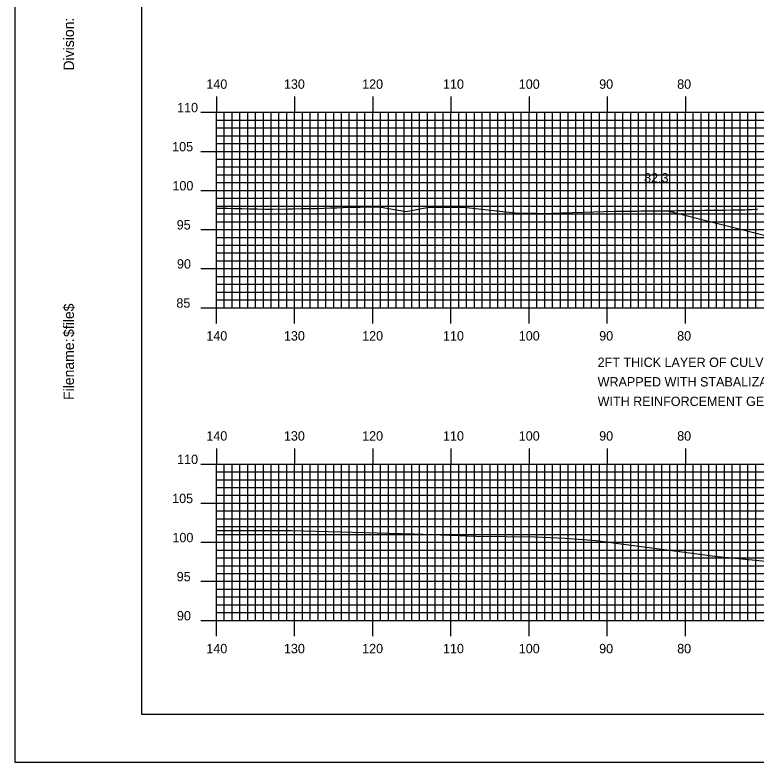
# Model space of a CAD drawing. Extents: x 1774777 to 1775120, y 442591 to 442811.
# Drawn here: x 1774776.9 to 1774871.7, y 442590.5 to 442686.1 of the extents above; entities that cross this region are included whole.
import ezdxf

# ---------------------------------------------------------------- set-up
doc = ezdxf.new("R2010")
doc.units = 0
for name, color, linetype in [('BORDER', 7, 'Continuous'), ('D_Roadway_FinishedGrade', 7, 'Continuous'), ('D_Text_Standard', 7, 'Continuous'), ('H_V ANNOTATION', 7, 'Continuous'), ('MAJOR', 7, 'Continuous'), ('MINOR', 7, 'Continuous'), ('PLOT BOUNDARY', 7, 'Continuous'), ('S_Roadway_Centerline', 7, 'Continuous')]:
    doc.layers.add(name, color=color, linetype=linetype)

msp = doc.modelspace()

# ---------------------------------------------------------------- linework, layer by layer
at = {"layer": 'BORDER'}
msp.add_lwpolyline([(1774793.085, 442596.665), (1775113.085, 442596.665), (1775113.085, 442806.665), (1774793.085, 442806.665)], close=True, dxfattribs=at)
at = {"layer": 'D_Roadway_FinishedGrade'}
for p, q in [((1774871.566, 442661.25), (1774871.566, 442661.25)), ((1774873.784, 442657.665), (1774860.231, 442661.061))]:
    msp.add_line(p, q, dxfattribs=at)
at = {"layer": 'MAJOR'}
for p, q in [((1774802.685, 442675.669), (1774802.685, 442673.665)), ((1774812.685, 442675.669), (1774812.685, 442673.665)), ((1774822.685, 442675.669), (1774822.685, 442673.665)), ((1774832.685, 442675.669), (1774832.685, 442673.665)), ((1774842.685, 442675.669), (1774842.685, 442673.665)), ((1774852.685, 442675.669), (1774852.685, 442673.665)), ((1774862.685, 442675.669), (1774862.685, 442673.665)), ((1774800.681, 442673.665), (1774802.685, 442673.665)), ((1774802.685, 442673.665), (1775082.685, 442673.665)), ((1774802.685, 442648.665), (1774802.685, 442673.665)), ((1774802.685, 442648.665), (1774802.685, 442673.665)), ((1774802.685, 442673.665), (1775082.685, 442673.665)), ((1774812.685, 442648.665), (1774812.685, 442673.665)), ((1774822.685, 442648.665), (1774822.685, 442673.665)), ((1774832.685, 442648.665), (1774832.685, 442673.665)), ((1774842.685, 442648.665), (1774842.685, 442673.665)), ((1774852.685, 442648.665), (1774852.685, 442673.665)), ((1774862.685, 442648.665), (1774862.685, 442673.665)), ((1774800.681, 442668.665), (1774802.685, 442668.665)), ((1774802.685, 442668.665), (1775082.685, 442668.665)), ((1774800.681, 442663.665), (1774802.685, 442663.665)), ((1774802.685, 442663.665), (1775082.685, 442663.665)), ((1774800.681, 442658.665), (1774802.685, 442658.665)), ((1774802.685, 442658.665), (1775082.685, 442658.665)), ((1774800.681, 442653.665), (1774802.685, 442653.665)), ((1774802.685, 442653.665), (1775082.685, 442653.665)), ((1774800.681, 442648.665), (1774802.685, 442648.665)), ((1774802.685, 442648.665), (1775082.685, 442648.665)), ((1774802.685, 442648.665), (1775082.685, 442648.665)), ((1774802.685, 442646.661), (1774802.685, 442648.665)), ((1774812.685, 442646.661), (1774812.685, 442648.665)), ((1774822.685, 442646.661), (1774822.685, 442648.665)), ((1774832.685, 442646.661), (1774832.685, 442648.665)), ((1774842.685, 442646.661), (1774842.685, 442648.665)), ((1774852.685, 442646.661), (1774852.685, 442648.665)), ((1774862.685, 442646.661), (1774862.685, 442648.665)), ((1774802.685, 442630.669), (1774802.685, 442628.665)), ((1774812.685, 442630.669), (1774812.685, 442628.665)), ((1774822.685, 442630.669), (1774822.685, 442628.665)), ((1774832.685, 442630.669), (1774832.685, 442628.665)), ((1774842.685, 442630.669), (1774842.685, 442628.665)), ((1774852.685, 442630.669), (1774852.685, 442628.665)), ((1774862.685, 442630.669), (1774862.685, 442628.665)), ((1774800.681, 442628.665), (1774802.685, 442628.665)), ((1774802.685, 442628.665), (1775082.685, 442628.665)), ((1774802.685, 442608.665), (1774802.685, 442628.665)), ((1774802.685, 442608.665), (1774802.685, 442628.665)), ((1774802.685, 442628.665), (1775082.685, 442628.665)), ((1774812.685, 442608.665), (1774812.685, 442628.665)), ((1774822.685, 442608.665), (1774822.685, 442628.665)), ((1774832.685, 442608.665), (1774832.685, 442628.665)), ((1774842.685, 442608.665), (1774842.685, 442628.665)), ((1774852.685, 442608.665), (1774852.685, 442628.665)), ((1774862.685, 442608.665), (1774862.685, 442628.665)), ((1774800.681, 442623.665), (1774802.685, 442623.665)), ((1774802.685, 442623.665), (1775082.685, 442623.665)), ((1774800.681, 442618.665), (1774802.685, 442618.665)), ((1774802.685, 442618.665), (1775082.685, 442618.665)), ((1774800.681, 442613.665), (1774802.685, 442613.665)), ((1774802.685, 442613.665), (1775082.685, 442613.665)), ((1774800.681, 442608.665), (1774802.685, 442608.665)), ((1774802.685, 442608.665), (1775082.685, 442608.665)), ((1774802.685, 442608.665), (1775082.685, 442608.665)), ((1774802.685, 442606.661), (1774802.685, 442608.665)), ((1774812.685, 442606.661), (1774812.685, 442608.665)), ((1774822.685, 442606.661), (1774822.685, 442608.665)), ((1774832.685, 442606.661), (1774832.685, 442608.665)), ((1774842.685, 442606.661), (1774842.685, 442608.665)), ((1774852.685, 442606.661), (1774852.685, 442608.665)), ((1774862.685, 442606.661), (1774862.685, 442608.665))]:
    msp.add_line(p, q, dxfattribs=at)
at = {"layer": 'MINOR'}
for p, q in [((1774803.685, 442648.665), (1774803.685, 442673.665)), ((1774804.685, 442648.665), (1774804.685, 442673.665)), ((1774805.685, 442648.665), (1774805.685, 442673.665)), ((1774806.685, 442648.665), (1774806.685, 442673.665)), ((1774807.685, 442648.665), (1774807.685, 442673.665)), ((1774808.685, 442648.665), (1774808.685, 442673.665)), ((1774809.685, 442648.665), (1774809.685, 442673.665)), ((1774810.685, 442648.665), (1774810.685, 442673.665)), ((1774811.685, 442648.665), (1774811.685, 442673.665)), ((1774813.685, 442648.665), (1774813.685, 442673.665)), ((1774814.685, 442648.665), (1774814.685, 442673.665)), ((1774815.685, 442648.665), (1774815.685, 442673.665)), ((1774816.685, 442648.665), (1774816.685, 442673.665)), ((1774817.685, 442648.665), (1774817.685, 442673.665)), ((1774818.685, 442648.665), (1774818.685, 442673.665)), ((1774819.685, 442648.665), (1774819.685, 442673.665)), ((1774820.685, 442648.665), (1774820.685, 442673.665)), ((1774821.685, 442648.665), (1774821.685, 442673.665)), ((1774823.685, 442648.665), (1774823.685, 442673.665)), ((1774824.685, 442648.665), (1774824.685, 442673.665)), ((1774825.685, 442648.665), (1774825.685, 442673.665)), ((1774826.685, 442648.665), (1774826.685, 442673.665)), ((1774827.685, 442648.665), (1774827.685, 442673.665)), ((1774828.685, 442648.665), (1774828.685, 442673.665)), ((1774829.685, 442648.665), (1774829.685, 442673.665)), ((1774830.685, 442648.665), (1774830.685, 442673.665)), ((1774831.685, 442648.665), (1774831.685, 442673.665)), ((1774833.685, 442648.665), (1774833.685, 442673.665)), ((1774834.685, 442648.665), (1774834.685, 442673.665)), ((1774835.685, 442648.665), (1774835.685, 442673.665)), ((1774836.685, 442648.665), (1774836.685, 442673.665)), ((1774837.685, 442648.665), (1774837.685, 442673.665)), ((1774838.685, 442648.665), (1774838.685, 442673.665)), ((1774839.685, 442648.665), (1774839.685, 442673.665)), ((1774840.685, 442648.665), (1774840.685, 442673.665)), ((1774841.685, 442648.665), (1774841.685, 442673.665)), ((1774843.685, 442648.665), (1774843.685, 442673.665)), ((1774844.685, 442648.665), (1774844.685, 442673.665)), ((1774845.685, 442648.665), (1774845.685, 442673.665)), ((1774846.685, 442648.665), (1774846.685, 442673.665)), ((1774847.685, 442648.665), (1774847.685, 442673.665)), ((1774848.685, 442648.665), (1774848.685, 442673.665)), ((1774849.685, 442648.665), (1774849.685, 442673.665)), ((1774850.685, 442648.665), (1774850.685, 442673.665)), ((1774851.685, 442648.665), (1774851.685, 442673.665)), ((1774853.685, 442648.665), (1774853.685, 442673.665)), ((1774854.685, 442648.665), (1774854.685, 442673.665)), ((1774855.685, 442648.665), (1774855.685, 442673.665)), ((1774856.685, 442648.665), (1774856.685, 442673.665)), ((1774857.685, 442648.665), (1774857.685, 442673.665)), ((1774858.685, 442648.665), (1774858.685, 442673.665)), ((1774859.685, 442648.665), (1774859.685, 442673.665)), ((1774860.685, 442648.665), (1774860.685, 442673.665)), ((1774861.685, 442648.665), (1774861.685, 442673.665)), ((1774863.685, 442648.665), (1774863.685, 442673.665)), ((1774864.685, 442648.665), (1774864.685, 442673.665)), ((1774865.685, 442648.665), (1774865.685, 442673.665)), ((1774866.685, 442648.665), (1774866.685, 442673.665)), ((1774867.685, 442648.665), (1774867.685, 442673.665)), ((1774868.685, 442648.665), (1774868.685, 442673.665)), ((1774869.685, 442648.665), (1774869.685, 442673.665)), ((1774870.685, 442648.665), (1774870.685, 442673.665)), ((1774871.685, 442648.665), (1774871.685, 442673.665)), ((1774802.685, 442672.665), (1775082.685, 442672.665)), ((1774802.685, 442672.665), (1774804.689, 442672.665)), ((1774802.685, 442671.665), (1775082.685, 442671.665)), ((1774802.685, 442671.665), (1774804.689, 442671.665)), ((1774802.685, 442670.665), (1775082.685, 442670.665)), ((1774802.685, 442670.665), (1774804.689, 442670.665)), ((1774802.685, 442669.665), (1775082.685, 442669.665)), ((1774802.685, 442669.665), (1774804.689, 442669.665)), ((1774802.685, 442667.665), (1775082.685, 442667.665)), ((1774802.685, 442667.665), (1774804.689, 442667.665)), ((1774802.685, 442666.665), (1775082.685, 442666.665)), ((1774802.685, 442666.665), (1774804.689, 442666.665)), ((1774802.685, 442665.665), (1775082.685, 442665.665)), ((1774802.685, 442665.665), (1774804.689, 442665.665)), ((1774802.685, 442664.665), (1775082.685, 442664.665)), ((1774802.685, 442664.665), (1774804.689, 442664.665)), ((1774802.685, 442662.665), (1775082.685, 442662.665)), ((1774802.685, 442662.665), (1774804.689, 442662.665)), ((1774802.685, 442661.665), (1775082.685, 442661.665)), ((1774802.685, 442661.665), (1774804.689, 442661.665)), ((1774802.685, 442660.665), (1775082.685, 442660.665)), ((1774802.685, 442660.665), (1774804.689, 442660.665)), ((1774802.685, 442659.665), (1775082.685, 442659.665)), ((1774802.685, 442659.665), (1774804.689, 442659.665)), ((1774802.685, 442657.665), (1775082.685, 442657.665)), ((1774802.685, 442657.665), (1774804.689, 442657.665)), ((1774802.685, 442656.665), (1775082.685, 442656.665)), ((1774802.685, 442656.665), (1774804.689, 442656.665)), ((1774802.685, 442655.665), (1775082.685, 442655.665)), ((1774802.685, 442655.665), (1774804.689, 442655.665)), ((1774802.685, 442654.665), (1775082.685, 442654.665)), ((1774802.685, 442654.665), (1774804.689, 442654.665)), ((1774802.685, 442652.665), (1775082.685, 442652.665)), ((1774802.685, 442652.665), (1774804.689, 442652.665)), ((1774802.685, 442651.665), (1775082.685, 442651.665)), ((1774802.685, 442651.665), (1774804.689, 442651.665)), ((1774802.685, 442650.665), (1775082.685, 442650.665)), ((1774802.685, 442650.665), (1774804.689, 442650.665)), ((1774802.685, 442649.665), (1775082.685, 442649.665)), ((1774802.685, 442649.665), (1774804.689, 442649.665)), ((1774803.685, 442608.665), (1774803.685, 442628.665)), ((1774804.685, 442608.665), (1774804.685, 442628.665)), ((1774805.685, 442608.665), (1774805.685, 442628.665)), ((1774806.685, 442608.665), (1774806.685, 442628.665)), ((1774807.685, 442608.665), (1774807.685, 442628.665)), ((1774808.685, 442608.665), (1774808.685, 442628.665)), ((1774809.685, 442608.665), (1774809.685, 442628.665)), ((1774810.685, 442608.665), (1774810.685, 442628.665)), ((1774811.685, 442608.665), (1774811.685, 442628.665)), ((1774813.685, 442608.665), (1774813.685, 442628.665)), ((1774814.685, 442608.665), (1774814.685, 442628.665)), ((1774815.685, 442608.665), (1774815.685, 442628.665)), ((1774816.685, 442608.665), (1774816.685, 442628.665)), ((1774817.685, 442608.665), (1774817.685, 442628.665)), ((1774818.685, 442608.665), (1774818.685, 442628.665)), ((1774819.685, 442608.665), (1774819.685, 442628.665)), ((1774820.685, 442608.665), (1774820.685, 442628.665)), ((1774821.685, 442608.665), (1774821.685, 442628.665)), ((1774823.685, 442608.665), (1774823.685, 442628.665)), ((1774824.685, 442608.665), (1774824.685, 442628.665)), ((1774825.685, 442608.665), (1774825.685, 442628.665)), ((1774826.685, 442608.665), (1774826.685, 442628.665)), ((1774827.685, 442608.665), (1774827.685, 442628.665)), ((1774828.685, 442608.665), (1774828.685, 442628.665)), ((1774829.685, 442608.665), (1774829.685, 442628.665)), ((1774830.685, 442608.665), (1774830.685, 442628.665)), ((1774831.685, 442608.665), (1774831.685, 442628.665)), ((1774833.685, 442608.665), (1774833.685, 442628.665)), ((1774834.685, 442608.665), (1774834.685, 442628.665)), ((1774835.685, 442608.665), (1774835.685, 442628.665)), ((1774836.685, 442608.665), (1774836.685, 442628.665)), ((1774837.685, 442608.665), (1774837.685, 442628.665)), ((1774838.685, 442608.665), (1774838.685, 442628.665)), ((1774839.685, 442608.665), (1774839.685, 442628.665)), ((1774840.685, 442608.665), (1774840.685, 442628.665)), ((1774841.685, 442608.665), (1774841.685, 442628.665)), ((1774843.685, 442608.665), (1774843.685, 442628.665)), ((1774844.685, 442608.665), (1774844.685, 442628.665)), ((1774845.685, 442608.665), (1774845.685, 442628.665)), ((1774846.685, 442608.665), (1774846.685, 442628.665)), ((1774847.685, 442608.665), (1774847.685, 442628.665)), ((1774848.685, 442608.665), (1774848.685, 442628.665)), ((1774849.685, 442608.665), (1774849.685, 442628.665)), ((1774850.685, 442608.665), (1774850.685, 442628.665)), ((1774851.685, 442608.665), (1774851.685, 442628.665)), ((1774853.685, 442608.665), (1774853.685, 442628.665)), ((1774854.685, 442608.665), (1774854.685, 442628.665)), ((1774855.685, 442608.665), (1774855.685, 442628.665)), ((1774856.685, 442608.665), (1774856.685, 442628.665)), ((1774857.685, 442608.665), (1774857.685, 442628.665)), ((1774858.685, 442608.665), (1774858.685, 442628.665)), ((1774859.685, 442608.665), (1774859.685, 442628.665)), ((1774860.685, 442608.665), (1774860.685, 442628.665)), ((1774861.685, 442608.665), (1774861.685, 442628.665)), ((1774863.685, 442608.665), (1774863.685, 442628.665)), ((1774864.685, 442608.665), (1774864.685, 442628.665)), ((1774865.685, 442608.665), (1774865.685, 442628.665)), ((1774866.685, 442608.665), (1774866.685, 442628.665)), ((1774867.685, 442608.665), (1774867.685, 442628.665)), ((1774868.685, 442608.665), (1774868.685, 442628.665)), ((1774869.685, 442608.665), (1774869.685, 442628.665)), ((1774870.685, 442608.665), (1774870.685, 442628.665)), ((1774871.685, 442608.665), (1774871.685, 442628.665)), ((1774802.685, 442627.665), (1775082.685, 442627.665)), ((1774802.685, 442627.665), (1774804.689, 442627.665)), ((1774802.685, 442626.665), (1775082.685, 442626.665)), ((1774802.685, 442626.665), (1774804.689, 442626.665)), ((1774802.685, 442625.665), (1775082.685, 442625.665)), ((1774802.685, 442625.665), (1774804.689, 442625.665)), ((1774802.685, 442624.665), (1775082.685, 442624.665)), ((1774802.685, 442624.665), (1774804.689, 442624.665)), ((1774802.685, 442622.665), (1775082.685, 442622.665)), ((1774802.685, 442622.665), (1774804.689, 442622.665)), ((1774802.685, 442621.665), (1775082.685, 442621.665)), ((1774802.685, 442621.665), (1774804.689, 442621.665)), ((1774802.685, 442620.665), (1775082.685, 442620.665)), ((1774802.685, 442620.665), (1774804.689, 442620.665)), ((1774802.685, 442619.665), (1775082.685, 442619.665)), ((1774802.685, 442619.665), (1774804.689, 442619.665)), ((1774802.685, 442617.665), (1775082.685, 442617.665)), ((1774802.685, 442617.665), (1774804.689, 442617.665)), ((1774802.685, 442616.665), (1775082.685, 442616.665)), ((1774802.685, 442616.665), (1774804.689, 442616.665)), ((1774802.685, 442615.665), (1775082.685, 442615.665)), ((1774802.685, 442615.665), (1774804.689, 442615.665)), ((1774802.685, 442614.665), (1775082.685, 442614.665)), ((1774802.685, 442614.665), (1774804.689, 442614.665)), ((1774802.685, 442612.665), (1775082.685, 442612.665)), ((1774802.685, 442612.665), (1774804.689, 442612.665)), ((1774802.685, 442611.665), (1775082.685, 442611.665)), ((1774802.685, 442611.665), (1774804.689, 442611.665)), ((1774802.685, 442610.665), (1775082.685, 442610.665)), ((1774802.685, 442610.665), (1774804.689, 442610.665)), ((1774802.685, 442609.665), (1775082.685, 442609.665)), ((1774802.685, 442609.665), (1774804.689, 442609.665))]:
    msp.add_line(p, q, dxfattribs=at)
at = {"layer": 'PLOT BOUNDARY'}
msp.add_lwpolyline([(1774776.898, 442590.547), (1775116.898, 442590.547), (1775116.898, 442810.547), (1774776.898, 442810.547)], close=True, dxfattribs=at)
at = {"layer": 'S_Roadway_Centerline'}
for points in [[(1774802.685, 442661.403), (1774803.27, 442661.392), (1774804.077, 442661.376), (1774804.963, 442661.358), (1774805.915, 442661.339), (1774806.914, 442661.32), (1774807.929, 442661.302), (1774808.92, 442661.286), (1774809.837, 442661.273), (1774811.846, 442661.325), (1774812.46, 442661.311), (1774813.57, 442661.356), (1774814.155, 442661.35), (1774814.846, 442661.356), (1774815.613, 442661.372), (1774816.427, 442661.396), (1774817.26, 442661.423), (1774818.091, 442661.452), (1774818.9, 442661.481), (1774819.672, 442661.506), (1774820.395, 442661.527), (1774821.06, 442661.542), (1774821.66, 442661.548), (1774823.521, 442661.548), (1774826.973, 442660.977), (1774829.862, 442661.518), (1774832.128, 442661.503), (1774834.294, 442661.516), (1774841.282, 442660.751), (1774842.231, 442660.745), (1774842.698, 442660.742), (1774843.149, 442660.74), (1774843.573, 442660.737), (1774843.956, 442660.735), (1774844.075, 442660.735), (1774844.198, 442660.734), (1774853.657, 442661.02), (1774854.201, 442661.021), (1774854.765, 442661.023), (1774855.898, 442661.028), (1774856.446, 442661.031), (1774856.971, 442661.035), (1774857.465, 442661.038), (1774857.921, 442661.041), (1774858.335, 442661.044), (1774858.646, 442661.046), (1774858.983, 442661.049), (1774859.341, 442661.052), (1774859.716, 442661.056), (1774860.101, 442661.06), (1774860.493, 442661.065), (1774860.888, 442661.069), (1774861.28, 442661.074), (1774861.667, 442661.078), (1774862.043, 442661.083), (1774862.406, 442661.087), (1774862.81, 442661.093), (1774863.282, 442661.099), (1774863.825, 442661.106), (1774864.446, 442661.114), (1774865.15, 442661.124), (1774866.815, 442661.147), (1774867.767, 442661.161), (1774868.777, 442661.175), (1774869.813, 442661.19), (1774869.877, 442661.191), (1774869.923, 442661.192), (1774870.284, 442661.204), (1774870.571, 442661.214), (1774870.885, 442661.226), (1774871.219, 442661.238), (1774871.566, 442661.25), (1774871.921, 442661.263)], [(1774802.685, 442620.156), (1774803.353, 442620.171), (1774812.276, 442620.159), (1774827.959, 442619.723), (1774835.898, 442619.452), (1774843.484, 442619.37), (1774847.306, 442619.183), (1774851.212, 442618.888), (1774866.468, 442616.902), (1774875.527, 442615.987)]]:
    msp.add_lwpolyline(points, dxfattribs=at)

# ---------------------------------------------------------------- texts
at = {"layer": 'BORDER'}
for s, p in [('Division:', (1774784.455, 442678.997)), ('$file$', (1774784.455, 442644.916)), ('Filename:', (1774784.455, 442636.862))]:
    msp.add_text(s, height=1.3392, rotation=90, dxfattribs=at).set_placement(p)
at = {"layer": 'D_Text_Standard'}
for s, p in [("82.3'", (1774857.405, 442664.682)), ('2FT THICK LAYER OF CULVERT BEDDING STONE', (1774851.46, 442641.086)), ('WRAPPED WITH STABALIZATION GEOTEXTILE AND', (1774851.46, 442638.586)), ('WITH REINFORCEMENT GEOGRID AT CENTER', (1774851.46, 442636.086))]:
    msp.add_text(s, height=1.2, dxfattribs=at).set_placement(p)
at = {"layer": 'H_V ANNOTATION'}
for s, p in [('140', (1774801.39, 442676.665)), ('130', (1774811.315, 442676.665)), ('120', (1774821.326, 442676.665)), ('110', (1774831.668, 442676.665)), ('100', (1774841.369, 442676.665)), ('90', (1774851.657, 442676.665)), ('80', (1774861.636, 442676.665)), ('110', (1774797.652, 442673.665)), ('105', (1774797.02, 442668.665)), ('100', (1774797.052, 442663.665)), ('95', (1774797.598, 442658.665)), ('90', (1774797.63, 442653.665)), ('85', (1774797.555, 442648.665)), ('140', (1774801.39, 442644.465)), ('130', (1774811.315, 442644.465)), ('120', (1774821.326, 442644.465)), ('110', (1774831.668, 442644.465)), ('100', (1774841.369, 442644.465)), ('90', (1774851.657, 442644.465)), ('80', (1774861.636, 442644.465)), ('140', (1774801.39, 442631.665)), ('130', (1774811.315, 442631.665)), ('120', (1774821.326, 442631.665)), ('110', (1774831.668, 442631.665)), ('100', (1774841.369, 442631.665)), ('90', (1774851.657, 442631.665)), ('80', (1774861.636, 442631.665)), ('110', (1774797.652, 442628.665)), ('105', (1774797.02, 442623.665)), ('100', (1774797.052, 442618.665)), ('95', (1774797.598, 442613.665)), ('90', (1774797.63, 442608.665)), ('140', (1774801.39, 442604.465)), ('130', (1774811.315, 442604.465)), ('120', (1774821.326, 442604.465)), ('110', (1774831.668, 442604.465)), ('100', (1774841.369, 442604.465)), ('90', (1774851.657, 442604.465)), ('80', (1774861.636, 442604.465))]:
    msp.add_text(s, height=1.2, dxfattribs=at).set_placement(p)
at = {"layer": 'MAJOR'}
for p in [(1774802.676, 442648.665), (1774802.676, 442608.665)]:
    msp.add_text('-', height=0.012, dxfattribs=at).set_placement(p)

doc.saveas('drawing.dxf')
